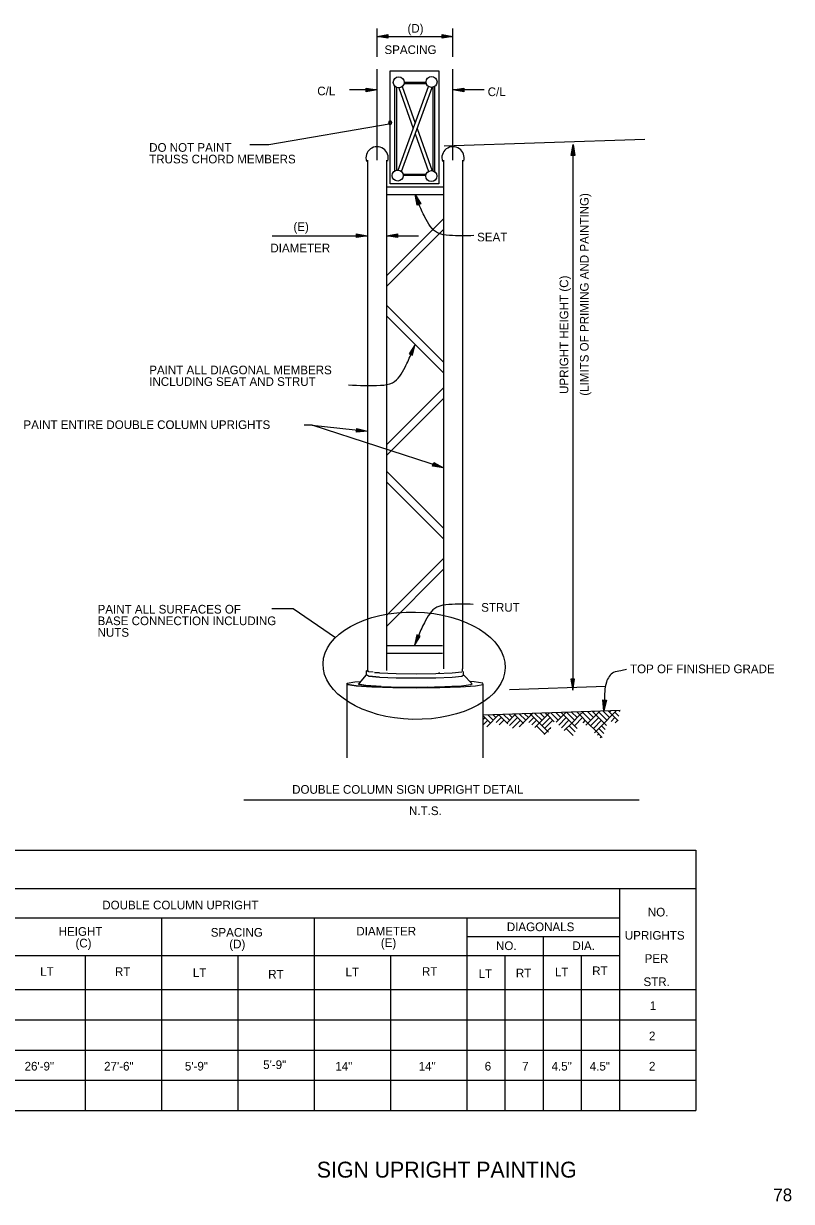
# Model space of a CAD drawing. Extents: x 10268852 to 10269008, y 2142584 to 2142686.
# Drawn here: x 10268947.8 to 10269008.1, y 2142586.4 to 2142678.9 of the extents above; entities that cross this region are included whole.
import ezdxf

# ---------------------------------------------------------------- set-up
doc = ezdxf.new("R2010")
doc.units = 0
for name, color, linetype in [('SignDetail', 7, 'Continuous'), ('TextDetails', 7, 'Continuous'), ('TextLabel', 7, 'Continuous'), ('TextMisc', 7, 'Continuous'), ('TextShtNo', 7, 'Continuous'), ('TextTables', 7, 'Continuous')]:
    doc.layers.add(name, color=color, linetype=linetype)

msp = doc.modelspace()

# ---------------------------------------------------------------- linework, layer by layer
at = {"layer": 'SignDetail'}
for p, q in [((10268976.947, 2142667.345), (10268976.947, 2142673.991)), ((10268977.096, 2142667.402), (10268977.096, 2142673.895)), ((10268977.212, 2142667.407), (10268979.593, 2142673.968)), ((10268977.264, 2142673.866), (10268978.395, 2142670.668)), ((10268977.474, 2142667.287), (10268979.869, 2142673.887)), ((10268977.534, 2142673.965), (10268978.55, 2142671.094)), ((10268977.678, 2142674.208), (10268979.414, 2142674.208)), ((10268977.687, 2142674.304), (10268979.397, 2142674.304)), ((10268979.946, 2142667.35), (10268979.946, 2142673.914)), ((10268980.094, 2142667.262), (10268980.094, 2142673.989)), ((10268978.546, 2142670.241), (10268979.588, 2142667.296)), ((10268978.701, 2142670.668), (10268979.872, 2142667.357)), ((10268977.59, 2142667.092), (10268979.417, 2142667.092)), ((10268977.605, 2142666.997), (10268979.39, 2142666.997)), ((10268976.29, 2142666.083), (10268980.771, 2142666.083)), ((10268976.29, 2142665.488), (10268980.771, 2142665.488)), ((10268976.29, 2142659.1), (10268980.771, 2142663.582)), ((10268976.29, 2142658.258), (10268980.771, 2142662.74)), ((10268976.289, 2142662.251), (10268978.804, 2142662.251)), ((10268976.29, 2142656.8), (10268980.771, 2142652.318)), ((10268976.29, 2142655.957), (10268980.771, 2142651.475)), ((10268976.29, 2142645.818), (10268980.771, 2142650.3)), ((10268976.29, 2142644.976), (10268980.771, 2142649.458)), ((10268976.29, 2142643.765), (10268980.771, 2142639.283)), ((10268976.29, 2142642.922), (10268980.771, 2142638.441)), ((10268976.29, 2142632.406), (10268980.771, 2142636.888)), ((10268976.29, 2142631.564), (10268980.771, 2142636.046)), ((10268976.29, 2142630.061), (10268980.693, 2142630.061)), ((10268976.29, 2142629.465), (10268980.693, 2142629.465)), ((10268994.654, 2142624.959), (10268983.899, 2142624.593)), ((10268992.338, 2142624.186), (10268991.701, 2142624.823)), ((10268992.975, 2142624.823), (10268993.614, 2142624.184)), ((10268984.459, 2142623.974), (10268983.899, 2142624.533)), ((10268986.386, 2142624.61), (10268985.747, 2142623.971)), ((10268987.023, 2142623.973), (10268986.386, 2142624.61)), ((10268988.724, 2142623.124), (10268988.087, 2142623.76)), ((10268988.937, 2142624.61), (10268988.298, 2142623.971)), ((10268989.15, 2142624.397), (10268988.511, 2142623.758)), ((10268989.363, 2142624.184), (10268988.724, 2142623.545)), ((10268991.488, 2142624.61), (10268990.85, 2142623.971)), ((10268991.701, 2142624.397), (10268991.063, 2142623.758)), ((10268992.125, 2142623.973), (10268991.488, 2142624.61)), ((10268992.125, 2142623.973), (10268992.764, 2142623.334)), ((10268992.975, 2142624.397), (10268992.338, 2142623.76)), ((10268993.188, 2142624.184), (10268992.551, 2142623.547)), ((10268993.401, 2142623.971), (10268992.764, 2142623.334)), ((10268994.04, 2142624.61), (10268993.401, 2142623.971))]:
    msp.add_line(p, q, dxfattribs=at)
msp.add_lwpolyline([(10268980.402, 2142666.324), (10268976.576, 2142666.324), (10268976.576, 2142675.204), (10268980.402, 2142675.204)], close=True, dxfattribs=at)
for points in [[(10268974.8, 2142668.183), (10268974.8, 2142628.099)], [(10268976.289, 2142668.183), (10268976.289, 2142628.099)], [(10268980.771, 2142668.183), (10268980.771, 2142628.236)], [(10268982.26, 2142668.183), (10268982.26, 2142628.236)], [(10268975.859, 2142626.845), (10268974.673, 2142626.918), (10268974.076, 2142627.012), (10268974.16, 2142627.112), (10268974.719, 2142627.746), (10268974.914, 2142627.656), (10268975.737, 2142627.579)], [(10268975.232, 2142627.964), (10268974.914, 2142627.994), (10268974.719, 2142628.084), (10268974.882, 2142628.114)], [(10268975.737, 2142627.579), (10268974.914, 2142627.656), (10268974.719, 2142627.746), (10268974.719, 2142628.084)], [(10268974.914, 2142627.656), (10268974.719, 2142627.746)], [(10268974.914, 2142627.656), (10268974.719, 2142627.746)], [(10268974.719, 2142627.746), (10268974.914, 2142627.656), (10268975.737, 2142627.579), (10268977.045, 2142627.527), (10268978.613, 2142627.51)], [(10268974.914, 2142627.656), (10268975.737, 2142627.579)], [(10268974.914, 2142627.656), (10268975.737, 2142627.579)], [(10268975.737, 2142627.917), (10268975.347, 2142627.954)], [(10268975.347, 2142627.954), (10268975.737, 2142627.917), (10268977.045, 2142627.865), (10268978.613, 2142627.848)], [(10268975.737, 2142627.917), (10268977.045, 2142627.865), (10268978.613, 2142627.848), (10268980.169, 2142627.868)], [(10268975.737, 2142627.579), (10268977.045, 2142627.527), (10268978.613, 2142627.51)], [(10268975.737, 2142627.579), (10268977.046, 2142627.527)], [(10268975.737, 2142627.579), (10268977.045, 2142627.527), (10268978.613, 2142627.51), (10268980.169, 2142627.53)], [(10268975.737, 2142627.579), (10268977.046, 2142627.527)], [(10268977.045, 2142627.527), (10268978.613, 2142627.51)], [(10268977.045, 2142627.527), (10268978.613, 2142627.51)], [(10268977.673, 2142627.859), (10268977.678, 2142627.859)], [(10268978.613, 2142627.848), (10268980.169, 2142627.868), (10268981.443, 2142627.923)], [(10268978.613, 2142627.51), (10268980.169, 2142627.53), (10268981.443, 2142627.584)], [(10268978.613, 2142627.51), (10268980.169, 2142627.53)], [(10268978.613, 2142627.51), (10268980.169, 2142627.53)], [(10268978.613, 2142627.51), (10268980.169, 2142627.53)], [(10268980.169, 2142627.868), (10268981.443, 2142627.923)], [(10268980.169, 2142627.53), (10268981.444, 2142627.585)], [(10268980.169, 2142627.53), (10268981.444, 2142627.585)], [(10268980.169, 2142627.53), (10268981.443, 2142627.584)], [(10268980.169, 2142627.53), (10268981.443, 2142627.584)], [(10268980.487, 2142627.882), (10268980.369, 2142627.889), (10268980.487, 2142627.882)], [(10268980.487, 2142627.882), (10268980.369, 2142627.889), (10268980.487, 2142627.882)], [(10268981.443, 2142627.923), (10268982.217, 2142628.001)], [(10268981.443, 2142627.923), (10268982.217, 2142628.001)], [(10268981.443, 2142627.584), (10268982.217, 2142627.663), (10268982.356, 2142627.753)], [(10268981.443, 2142627.584), (10268982.217, 2142627.663), (10268982.356, 2142627.753), (10268983.01, 2142627.09)], [(10268981.443, 2142627.584), (10268982.217, 2142627.663)], [(10268981.444, 2142627.584), (10268982.217, 2142627.663)], [(10268981.444, 2142627.584), (10268982.217, 2142627.663)], [(10268982.217, 2142627.663), (10268982.356, 2142627.753), (10268982.356, 2142628.009)], [(10268982.217, 2142627.663), (10268982.356, 2142627.753)], [(10268982.217, 2142627.663), (10268982.356, 2142627.753)], [(10268982.26, 2142628.01), (10268982.26, 2142628.236)], [(10268978.642, 2142626.744), (10268976.782, 2142626.76), (10268975.135, 2142626.812), (10268973.899, 2142626.892), (10268973.223, 2142626.991), (10268973.189, 2142627.098), (10268973.801, 2142627.199), (10268974.265, 2142627.231)], [(10268973.189, 2142627.098), (10268973.802, 2142627.199)], [(10268973.189, 2142627.098), (10268973.223, 2142626.991), (10268973.899, 2142626.892), (10268975.135, 2142626.812), (10268976.782, 2142626.76), (10268978.642, 2142626.744)], [(10268973.19, 2142621.248), (10268973.19, 2142627.098), (10268973.801, 2142627.199), (10268974.265, 2142627.231)], [(10268973.801, 2142627.199), (10268974.265, 2142627.231)], [(10268974.673, 2142626.919), (10268974.144, 2142627.002)], [(10268974.673, 2142626.919), (10268974.144, 2142627.002)], [(10268974.673, 2142626.919), (10268974.786, 2142626.911)], [(10268974.673, 2142626.919), (10268974.786, 2142626.911)], [(10268975.859, 2142626.845), (10268977.453, 2142626.802)], [(10268977.453, 2142626.802), (10268979.214, 2142626.798)], [(10268977.628, 2142626.802), (10268979.214, 2142626.798)], [(10268977.628, 2142626.802), (10268979.214, 2142626.798)], [(10268978.642, 2142626.744), (10268980.489, 2142626.764), (10268982.103, 2142626.819), (10268983.287, 2142626.902), (10268983.899, 2142627.002), (10268983.865, 2142627.109), (10268983.189, 2142627.208), (10268982.873, 2142627.229)], [(10268978.642, 2142626.744), (10268980.489, 2142626.764), (10268982.103, 2142626.819)], [(10268979.214, 2142626.798), (10268980.873, 2142626.832)], [(10268979.214, 2142626.798), (10268979.493, 2142626.803)], [(10268979.214, 2142626.798), (10268979.493, 2142626.803)], [(10268980.873, 2142626.832), (10268982.177, 2142626.899), (10268982.929, 2142626.988), (10268983.012, 2142627.088)], [(10268981.426, 2142626.86), (10268982.177, 2142626.899), (10268982.929, 2142626.988)], [(10268981.426, 2142626.86), (10268982.177, 2142626.899), (10268982.929, 2142626.988)], [(10268982.103, 2142626.819), (10268983.287, 2142626.902), (10268983.899, 2142627.002), (10268983.865, 2142627.109), (10268983.189, 2142627.208), (10268982.873, 2142627.229)], [(10268983.899, 2142627.002), (10268983.865, 2142627.109), (10268983.19, 2142627.208), (10268982.873, 2142627.229)], [(10268982.929, 2142626.988), (10268982.951, 2142627.015)], [(10268982.929, 2142626.988), (10268982.951, 2142627.015)], [(10268983.899, 2142621.248), (10268983.899, 2142627.002)], [(10268985.908, 2142624.661), (10268986.173, 2142624.397)], [(10268986.32, 2142624.675), (10268986.386, 2142624.61)], [(10268986.456, 2142624.68), (10268986.386, 2142624.61)], [(10268986.732, 2142623.682), (10268987.774, 2142624.725)], [(10268987.235, 2142624.186), (10268986.732, 2142624.69)], [(10268987.449, 2142624.399), (10268987.144, 2142624.703)], [(10268989.014, 2142623.256), (10268987.552, 2142624.717)], [(10268987.964, 2142624.731), (10268988.511, 2142624.184)], [(10268988.376, 2142624.745), (10268988.724, 2142624.397)], [(10268988.788, 2142624.759), (10268988.937, 2142624.61)], [(10268989.097, 2142624.769), (10268988.937, 2142624.61)], [(10268989.787, 2142624.186), (10268989.2, 2142624.773)], [(10268990, 2142624.399), (10268989.612, 2142624.787)], [(10268989.633, 2142624.032), (10268990.415, 2142624.815)], [(10268991.274, 2142623.547), (10268990.019, 2142624.801)], [(10268990.431, 2142624.815), (10268991.063, 2142624.184)], [(10268990.843, 2142624.829), (10268991.276, 2142624.397)], [(10268991.255, 2142624.843), (10268991.488, 2142624.61)], [(10268991.297, 2142624.845), (10268991.276, 2142624.823)], [(10268991.738, 2142624.859), (10268991.488, 2142624.61)], [(10268991.954, 2142623.802), (10268993.057, 2142624.904)], [(10268992.551, 2142624.399), (10268992.079, 2142624.871)], [(10268993.597, 2142623.775), (10268992.487, 2142624.885)], [(10268992.62, 2142624.89), (10268992.551, 2142624.821)], [(10268993.311, 2142624.913), (10268993.827, 2142624.397)], [(10268993.723, 2142624.927), (10268994.04, 2142624.61)], [(10268993.938, 2142624.934), (10268993.827, 2142624.823)], [(10268994.379, 2142624.949), (10268994.04, 2142624.61)], [(10268994.566, 2142624.51), (10268994.253, 2142624.823)], [(10268994.636, 2142624.866), (10268994.547, 2142624.955)], [(10268984.035, 2142624.397), (10268983.899, 2142624.261)], [(10268984.248, 2142624.184), (10268983.899, 2142623.836)], [(10268984.167, 2142623.682), (10268985.12, 2142624.635)], [(10268984.245, 2142623.76), (10268984.253, 2142623.753)], [(10268984.671, 2142624.186), (10268984.252, 2142624.606)], [(10268984.458, 2142623.973), (10268984.485, 2142623.947)], [(10268984.884, 2142624.399), (10268984.664, 2142624.62)], [(10268985.308, 2142624.397), (10268984.919, 2142624.008)], [(10268985.059, 2142624.561), (10268985.134, 2142624.635)], [(10268985.817, 2142623.901), (10268985.084, 2142624.634)], [(10268985.521, 2142624.184), (10268985.158, 2142623.821)], [(10268985.321, 2142624.397), (10268985.287, 2142624.363)], [(10268985.497, 2142624.647), (10268985.96, 2142624.184)], [(10268985.534, 2142624.184), (10268985.515, 2142624.165)], [(10268985.747, 2142623.971), (10268985.742, 2142623.966)], [(10268986.599, 2142624.397), (10268985.97, 2142623.768)], [(10268986.812, 2142624.184), (10268986.198, 2142623.57)], [(10268986.81, 2142623.76), (10268986.817, 2142623.753)], [(10268987.023, 2142623.973), (10268987.049, 2142623.947)], [(10268987.872, 2142624.397), (10268987.483, 2142624.008)], [(10268988.085, 2142624.184), (10268987.722, 2142623.821)], [(10268988.298, 2142623.971), (10268987.961, 2142623.634)], [(10268989.474, 2142624.073), (10268988.937, 2142624.61)], [(10268990.424, 2142624.397), (10268989.84, 2142623.813)], [(10268990.637, 2142624.184), (10268990.047, 2142623.594)], [(10268990.85, 2142623.971), (10268990.254, 2142623.376)], [(10268991.123, 2142623.276), (10268990.639, 2142623.76)], [(10268991.914, 2142624.184), (10268991.727, 2142623.997)], [(10268993.483, 2142623.467), (10268993.19, 2142623.76)], [(10268994.253, 2142624.397), (10268993.943, 2142624.087)], [(10268994.496, 2142624.154), (10268994.04, 2142624.61)], [(10268994.466, 2142624.184), (10268994.267, 2142623.986)], [(10268988.676, 2142623.076), (10268989.216, 2142623.615)], [(10268989.148, 2142623.547), (10268989.167, 2142623.528)], [(10268990.971, 2142623.002), (10268990.426, 2142623.547)], [(10268992.764, 2142623.334), (10268992.641, 2142623.211)], [(10268993.254, 2142622.844), (10268992.764, 2142623.334)], [(10268992.977, 2142623.121), (10268992.87, 2142623.014)], [(10268993.369, 2142623.155), (10268992.977, 2142623.547)], [(10268993.19, 2142622.909), (10268993.098, 2142622.817)]]:
    msp.add_lwpolyline(points, dxfattribs=at)
for centre in [(10268977.255, 2142674.295), (10268979.829, 2142674.33), (10268977.173, 2142666.976), (10268979.817, 2142666.93)]:
    msp.add_circle(centre, 0.432, dxfattribs=at)
for centre, radius, start, end in [((10268976.572, 2142671.129), 0.133, 233.1476, 214.08238), ((10268975.548, 2142668.363), 0.876, 343.69915, 198.54837), ((10268981.519, 2142668.363), 0.876, 343.69915, 198.54837)]:
    msp.add_arc(centre, radius, start, end, dxfattribs=at)
at = {"layer": 'TextDetails'}
msp.add_line((10268965.077, 2142617.945), (10268996.143, 2142617.945), dxfattribs=at)
at = {"layer": 'TextLabel'}
for p, q in [((10268975.545, 2142676.308), (10268975.545, 2142678.512)), ((10268981.516, 2142676.308), (10268981.516, 2142678.512)), ((10268975.545, 2142677.904), (10268981.516, 2142677.904)), ((10268975.545, 2142668.183), (10268975.545, 2142675.32)), ((10268981.516, 2142668.183), (10268981.516, 2142675.32)), ((10268975.545, 2142673.696), (10268973.373, 2142673.696)), ((10268983.97, 2142673.696), (10268981.516, 2142673.696)), ((10268976.492, 2142671.023), (10268967.033, 2142669.376)), ((10268967.033, 2142669.376), (10268965.556, 2142669.376)), ((10268996.59, 2142669.813), (10268980.819, 2142669.276)), ((10268990.962, 2142626.653), (10268990.962, 2142669.169)), ((10268967.298, 2142662.251), (10268974.8, 2142662.251)), ((10268970.437, 2142647.373), (10268969.805, 2142647.373)), ((10268980.771, 2142644.01), (10268970.437, 2142647.373)), ((10268970.437, 2142647.373), (10268974.787, 2142646.891)), ((10268968.956, 2142632.939), (10268967.282, 2142632.939)), ((10268972.269, 2142630.677), (10268968.956, 2142632.939)), ((10268993.521, 2142626.831), (10268985.952, 2142626.574))]:
    msp.add_line(p, q, dxfattribs=at)
for points in [[(10268975.545, 2142677.904), (10268976.403, 2142678.048), (10268976.403, 2142677.76)], [(10268975.799, 2142677.904), (10268976.375, 2142677.993), (10268976.375, 2142677.815)], [(10268976.032, 2142677.904), (10268976.327, 2142677.952), (10268976.327, 2142677.856)], [(10268981.516, 2142677.904), (10268980.658, 2142677.76), (10268980.658, 2142678.048)], [(10268981.262, 2142677.904), (10268980.685, 2142677.814), (10268980.685, 2142677.993)], [(10268981.029, 2142677.904), (10268980.733, 2142677.856), (10268980.733, 2142677.952)], [(10268975.545, 2142673.696), (10268974.687, 2142673.552), (10268974.687, 2142673.84)], [(10268975.291, 2142673.696), (10268974.714, 2142673.607), (10268974.714, 2142673.785)], [(10268975.058, 2142673.696), (10268974.762, 2142673.648), (10268974.762, 2142673.744)], [(10268981.516, 2142673.696), (10268982.374, 2142673.84), (10268982.374, 2142673.552)], [(10268981.77, 2142673.696), (10268982.346, 2142673.785), (10268982.346, 2142673.607)], [(10268982.003, 2142673.696), (10268982.298, 2142673.744), (10268982.298, 2142673.648)], [(10268990.962, 2142669.419), (10268991.106, 2142668.561), (10268990.818, 2142668.561)], [(10268990.962, 2142669.165), (10268991.052, 2142668.588), (10268990.873, 2142668.588)], [(10268990.962, 2142668.931), (10268991.01, 2142668.636), (10268990.914, 2142668.636)], [(10268978.531, 2142665.488), (10268978.982, 2142664.744), (10268978.714, 2142664.638)], [(10268978.624, 2142665.252), (10268978.921, 2142664.75), (10268978.755, 2142664.683)], [(10268978.711, 2142665.035), (10268978.865, 2142664.779), (10268978.775, 2142664.743)], [(10268974.8, 2142662.251), (10268973.942, 2142662.107), (10268973.942, 2142662.395)], [(10268974.546, 2142662.251), (10268973.97, 2142662.162), (10268973.97, 2142662.34)], [(10268974.313, 2142662.251), (10268974.018, 2142662.203), (10268974.018, 2142662.299)], [(10268976.289, 2142662.251), (10268977.147, 2142662.395), (10268977.147, 2142662.107)], [(10268976.543, 2142662.251), (10268977.12, 2142662.341), (10268977.12, 2142662.162)], [(10268976.777, 2142662.251), (10268977.072, 2142662.3), (10268977.072, 2142662.203)], [(10268978.531, 2142653.716), (10268978.079, 2142652.973), (10268978.347, 2142652.866)], [(10268978.437, 2142653.48), (10268978.14, 2142652.978), (10268978.306, 2142652.912)], [(10268978.35, 2142653.264), (10268978.196, 2142653.007), (10268978.286, 2142652.972)], [(10268974.787, 2142646.891), (10268973.919, 2142646.83), (10268973.947, 2142647.117)], [(10268974.534, 2142646.915), (10268973.951, 2142646.882), (10268973.969, 2142647.06)], [(10268974.302, 2142646.938), (10268974.003, 2142646.919), (10268974.012, 2142647.014)], [(10268980.771, 2142644.009), (10268979.913, 2142644.152), (10268980.007, 2142644.425)], [(10268980.531, 2142644.092), (10268979.957, 2142644.195), (10268980.015, 2142644.364)], [(10268980.31, 2142644.168), (10268980.016, 2142644.218), (10268980.047, 2142644.309)], [(10268978.491, 2142630.061), (10268978.943, 2142630.804), (10268978.675, 2142630.911)], [(10268978.585, 2142630.297), (10268978.881, 2142630.799), (10268978.716, 2142630.865)], [(10268978.671, 2142630.513), (10268978.825, 2142630.77), (10268978.736, 2142630.805)], [(10268990.932, 2142626.554), (10268991.076, 2142627.412), (10268990.788, 2142627.412)], [(10268990.932, 2142626.808), (10268991.021, 2142627.385), (10268990.843, 2142627.385)], [(10268990.932, 2142627.041), (10268990.98, 2142627.337), (10268990.884, 2142627.337)], [(10268993.38, 2142624.922), (10268993.29, 2142625.787), (10268993.578, 2142625.769)], [(10268993.396, 2142625.175), (10268993.343, 2142625.756), (10268993.521, 2142625.745)], [(10268993.411, 2142625.408), (10268993.381, 2142625.705), (10268993.477, 2142625.699)]]:
    msp.add_lwpolyline(points, close=True, dxfattribs=at)
msp.add_ellipse((10268978.464, 2142628.471), major_axis=(7.162, -0.159), ratio=0.588001, dxfattribs=at)
for points in [[(10268983.151, 2142662.259), (10268981.239, 2142662.269), (10268980.292, 2142662.474), (10268979.31, 2142663.694), (10268978.8, 2142664.811), (10268978.531, 2142665.488)], [(10268973.309, 2142650.538), (10268975.822, 2142650.498), (10268976.769, 2142650.703), (10268977.751, 2142651.923), (10268978.261, 2142653.039), (10268978.531, 2142653.716)], [(10268983.111, 2142633.289), (10268981.199, 2142633.279), (10268980.253, 2142633.074), (10268979.27, 2142631.854), (10268978.761, 2142630.738), (10268978.491, 2142630.061)], [(10268995.154, 2142628.172), (10268994.709, 2142628.072), (10268994.144, 2142627.95), (10268993.577, 2142627.188), (10268993.43, 2142625.711), (10268993.38, 2142624.922)]]:
    msp.add_spline(points, degree=3, dxfattribs=at)
at = {"layer": 'TextTables'}
for p, q in [((10268900.595, 2142613.976), (10269000.595, 2142613.976)), ((10269000.595, 2142613.976), (10269000.595, 2142593.534)), ((10268900.595, 2142610.976), (10269000.595, 2142610.976)), ((10268994.595, 2142610.976), (10268994.595, 2142593.534)), ((10268922.595, 2142608.66), (10268994.595, 2142608.66)), ((10268958.595, 2142608.66), (10268958.595, 2142593.534)), ((10268970.595, 2142608.66), (10268970.595, 2142593.534)), ((10268982.595, 2142608.66), (10268982.595, 2142593.534)), ((10268982.595, 2142607.193), (10268994.595, 2142607.193)), ((10268988.595, 2142607.193), (10268988.595, 2142593.534)), ((10268922.595, 2142605.725), (10268994.595, 2142605.725)), ((10268952.595, 2142605.725), (10268952.595, 2142593.534)), ((10268964.595, 2142605.725), (10268964.595, 2142593.534)), ((10268976.595, 2142605.725), (10268976.595, 2142593.534)), ((10268985.595, 2142605.725), (10268985.595, 2142593.534)), ((10268991.595, 2142605.725), (10268991.595, 2142593.534)), ((10268900.595, 2142603.042), (10269000.595, 2142603.042)), ((10268900.595, 2142600.665), (10269000.595, 2142600.665)), ((10268900.595, 2142598.288), (10269000.595, 2142598.288)), ((10268900.595, 2142595.911), (10269000.595, 2142595.911)), ((10268900.595, 2142593.534), (10269000.595, 2142593.534))]:
    msp.add_line(p, q, dxfattribs=at)

# ---------------------------------------------------------------- texts
at = {"layer": 'TextDetails'}
for s, p in [('DOUBLE COLUMN SIGN UPRIGHT DETAIL', (10268968.873, 2142618.416)), ('N.T.S.', (10268978.061, 2142616.741))]:
    msp.add_text(s, height=0.68, dxfattribs=at).set_placement(p)
at = {"layer": 'TextLabel'}
for s, p in [('(D)', (10268977.939, 2142678.197)), ('SPACING', (10268976.13, 2142676.519)), ('C/L', (10268970.849, 2142673.276)), ('C/L', (10268984.247, 2142673.215)), ('DO NOT PAINT ', (10268957.634, 2142668.841)), ('TRUSS CHORD MEMBERS', (10268957.634, 2142667.929)), ('(E)', (10268968.973, 2142662.62)), ('SEAT', (10268983.415, 2142661.803)), ('DIAMETER', (10268967.164, 2142660.943)), ('PAINT ALL DIAGONAL MEMBERS', (10268957.638, 2142651.363)), ('INCLUDING SEAT AND STRUT', (10268957.638, 2142650.452)), ('PAINT ENTIRE DOUBLE COLUMN UPRIGHTS', (10268947.751, 2142647.065)), ('PAINT ALL SURFACES OF ', (10268953.578, 2142632.572)), ('STRUT', (10268983.735, 2142632.716)), ('BASE CONNECTION INCLUDING ', (10268953.578, 2142631.661)), ('NUTS', (10268953.578, 2142630.749)), ('TOP OF FINISHED GRADE', (10268995.435, 2142627.888))]:
    msp.add_text(s, height=0.68, dxfattribs=at).set_placement(p)
for s, p in [('(LIMITS OF PRIMING AND PAINTING)', (10268992.18, 2142649.681)), ('UPRIGHT HEIGHT (C)', (10268990.582, 2142649.822))]:
    msp.add_text(s, height=0.68, rotation=90, dxfattribs=at).set_placement(p)
at = {"layer": 'TextMisc'}
msp.add_text('    SIGN UPRIGHT PAINTING      ', height=1.25, rotation=360, dxfattribs=at).set_placement((10268968.954, 2142588.266))
at = {"layer": 'TextShtNo'}
msp.add_text('78', height=1, rotation=360, dxfattribs=at).set_placement((10269006.696, 2142586.409))
at = {"layer": 'TextTables'}
for s, p in [('DOUBLE COLUMN UPRIGHT', (10268953.947, 2142609.334)), ('NO.', (10268996.835, 2142608.779)), ('DIAGONALS', (10268985.749, 2142607.625)), ('HEIGHT', (10268950.518, 2142607.258)), ('SPACING', (10268962.474, 2142607.189)), ('DIAMETER', (10268973.92, 2142607.284)), ('(E)', (10268975.846, 2142606.373)), ('UPRIGHTS', (10268995.026, 2142606.957)), ('(C)', (10268951.84, 2142606.347)), ('(D)', (10268963.931, 2142606.277)), ('NO.', (10268984.9, 2142606.14)), ('DIA.', (10268990.906, 2142606.14)), ('PER', (10268996.582, 2142605.134)), ('LT', (10268949.068, 2142604.116)), ('RT', (10268954.941, 2142604.104)), ('LT', (10268961.068, 2142604.015)), ('RT', (10268966.991, 2142603.903)), ('LT', (10268973.068, 2142604.079)), ('RT', (10268979.078, 2142604.116)), ('LT', (10268983.53, 2142603.944)), ('RT', (10268986.461, 2142603.994)), ('LT', (10268989.53, 2142604.081)), ('RT', (10268992.461, 2142604.17)), ('STR.', (10268996.494, 2142603.312)), ('1', (10268996.983, 2142601.431)), ('2', (10268996.922, 2142599.054)), ('26\'-9"', (10268947.84, 2142596.677)), ('27\'-6"', (10268954.091, 2142596.677)), ('5\'-9"', (10268960.443, 2142596.677)), ('5\'-9"', (10268966.595, 2142596.798)), ('14"', (10268972.271, 2142596.677)), ('14"', (10268978.823, 2142596.677)), ('6', (10268984.012, 2142596.677)), ('7', (10268986.957, 2142596.677)), ('4.5"', (10268989.267, 2142596.677)), ('4.5"', (10268992.268, 2142596.677)), ('2', (10268996.922, 2142596.677))]:
    msp.add_text(s, height=0.68, dxfattribs=at).set_placement(p)

doc.saveas('drawing.dxf')
